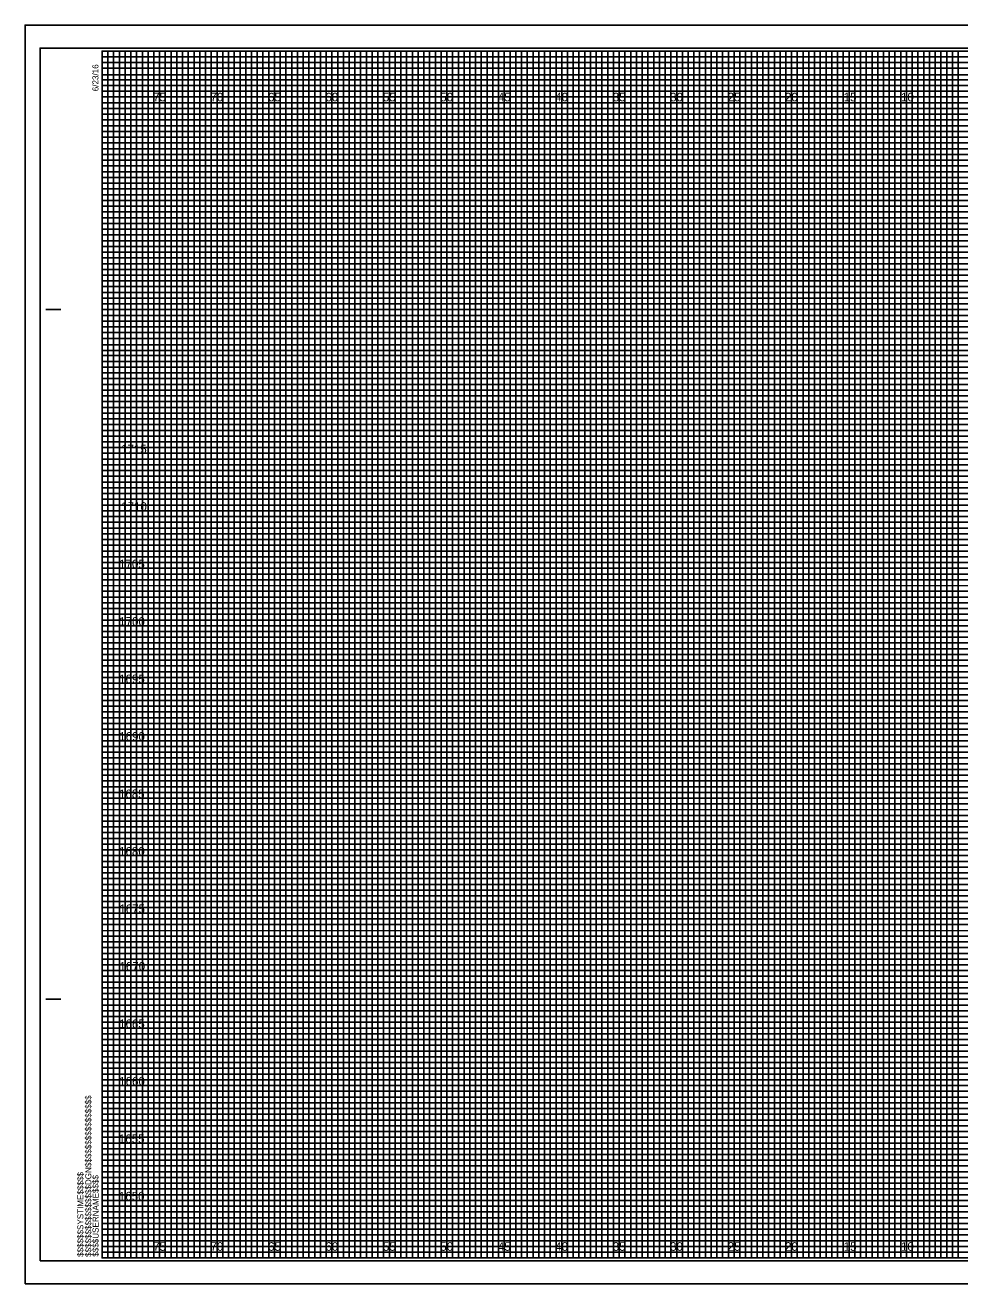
# Model space of a CAD drawing. Extents: x -407 to -239, y -3 to 766.
# Drawn here: x -407 to -325.7, y 326.6 to 436.1 of the extents above; entities that cross this region are included whole.
import ezdxf

# ---------------------------------------------------------------- set-up
doc = ezdxf.new("R2010")
doc.units = 0
for name, color, linetype in [('Raster_Level_0', 7, 'Continuous'), ('Scratch_Level_3', 7, 'Continuous'), ('Sheet Cross Section CELL', 7, 'Continuous'), ('Sheet Cross Section Grid Major CELL', 7, 'Continuous'), ('Sheet Cross Section Grid Middle CELL', 7, 'Continuous'), ('Sheet Cross Section Grid Minor 1 CELL', 7, 'Continuous'), ('Sheet Cross Section Grid Minor 2 CELL', 7, 'Continuous'), ('Sheet Cutting Line CELL', 7, 'Continuous'), ('Sheet DOT Grid CELL', 7, 'Continuous'), ('Sheet Plot Border Inside CELL', 7, 'Continuous'), ('Sheet Plot Border Outside CELL', 7, 'Continuous')]:
    doc.layers.add(name, color=color, linetype=linetype)

msp = doc.modelspace()

# ---------------------------------------------------------------- linework, layer by layer
at = {"layer": 'Sheet Cross Section CELL'}
for p, q in [((-405.22, 411.38), (-403.97, 411.38)), ((-405.17, 411.38), (-403.92, 411.38)), ((-405.22, 351.38), (-403.97, 351.38)), ((-405.17, 351.38), (-403.92, 351.38)), ((-400.32, 328.88), (-400.32, 328.88)), ((-400.32, 328.88), (-400.32, 328.88)), ((-400.32, 328.88), (-400.32, 328.88)), ((-400.32, 328.88), (-400.32, 328.88)), ((-400.32, 328.88), (-400.32, 328.88)), ((-400.32, 328.88), (-400.32, 328.88)), ((-400.32, 328.88), (-400.32, 328.88))]:
    msp.add_line(p, q, dxfattribs=at)
msp.add_lwpolyline([(-240.32, 433.88), (-400.32, 433.88), (-400.32, 328.88), (-240.32, 328.88)], close=True, dxfattribs=at)
at = {"layer": 'Sheet Cross Section Grid Major CELL'}
for p, q in [((-395.32, 433.88), (-400.32, 433.88)), ((-395.32, 328.88), (-395.32, 433.88)), ((-385.32, 433.88), (-390.32, 433.88)), ((-390.32, 433.88), (-390.32, 328.88)), ((-385.32, 328.88), (-385.32, 433.88)), ((-375.32, 433.88), (-380.32, 433.88)), ((-380.32, 433.88), (-380.32, 328.88)), ((-375.32, 328.88), (-375.32, 433.88)), ((-365.32, 433.88), (-370.32, 433.88)), ((-370.32, 433.88), (-370.32, 328.88)), ((-365.32, 328.88), (-365.32, 433.88)), ((-355.32, 433.88), (-360.32, 433.88)), ((-360.32, 433.88), (-360.32, 328.88)), ((-355.32, 328.88), (-355.32, 433.88)), ((-345.32, 433.88), (-350.32, 433.88)), ((-350.32, 433.88), (-350.32, 328.88)), ((-345.32, 328.88), (-345.32, 433.88)), ((-335.32, 433.88), (-340.32, 433.88)), ((-340.32, 433.88), (-340.32, 328.88)), ((-335.32, 328.88), (-335.32, 433.88)), ((-325.32, 433.88), (-330.32, 433.88)), ((-330.32, 433.88), (-330.32, 328.88)), ((-390.32, 328.88), (-395.32, 328.88)), ((-380.32, 328.88), (-385.32, 328.88)), ((-370.32, 328.88), (-375.32, 328.88)), ((-360.32, 328.88), (-365.32, 328.88)), ((-350.32, 328.88), (-355.32, 328.88)), ((-340.32, 328.88), (-345.32, 328.88)), ((-330.32, 328.88), (-335.32, 328.88))]:
    msp.add_line(p, q, dxfattribs=at)
for points in [[(-400.32, 428.88), (-240.32, 428.88), (-240.32, 423.88), (-400.32, 423.88)], [(-400.32, 418.88), (-240.32, 418.88), (-240.32, 413.88), (-400.32, 413.88)], [(-400.32, 408.88), (-240.32, 408.88), (-240.32, 403.88), (-400.32, 403.88)], [(-400.32, 398.88), (-240.32, 398.88), (-240.32, 393.88), (-400.32, 393.88)], [(-400.32, 388.88), (-240.32, 388.88), (-240.32, 383.88), (-400.32, 383.88)], [(-400.32, 378.88), (-240.32, 378.88), (-240.32, 373.88), (-400.32, 373.88)], [(-400.32, 368.88), (-240.32, 368.88), (-240.32, 363.88), (-400.32, 363.88)], [(-400.32, 358.88), (-240.32, 358.88), (-240.32, 353.88), (-400.32, 353.88)], [(-400.32, 348.88), (-240.32, 348.88), (-240.32, 343.88), (-400.32, 343.88)], [(-400.32, 338.88), (-240.32, 338.88), (-240.32, 333.88), (-400.32, 333.88)]]:
    msp.add_lwpolyline(points, dxfattribs=at)
at = {"layer": 'Sheet Cross Section Grid Middle CELL'}
for points in [[(-400.32, 433.88), (-397.82, 433.88), (-397.82, 328.88), (-392.82, 328.88), (-392.82, 433.88), (-387.82, 433.88), (-387.82, 328.88), (-382.82, 328.88), (-382.82, 433.88), (-377.82, 433.88), (-377.82, 328.88), (-372.82, 328.88), (-372.82, 433.88), (-367.82, 433.88), (-367.82, 328.88), (-362.82, 328.88), (-362.82, 433.88), (-357.82, 433.88), (-357.82, 328.88), (-352.82, 328.88), (-352.82, 433.88), (-347.82, 433.88), (-347.82, 328.88), (-342.82, 328.88), (-342.82, 433.88), (-337.82, 433.88), (-337.82, 328.88), (-332.82, 328.88), (-332.82, 433.88), (-327.82, 433.88), (-327.82, 328.88), (-322.82, 328.88)], [(-400.32, 431.38), (-262.82, 431.38)], [(-400.32, 421.38), (-240.32, 421.38), (-240.32, 426.38), (-400.32, 426.38)], [(-400.32, 411.38), (-240.32, 411.38), (-240.32, 416.38), (-400.32, 416.38)], [(-400.32, 401.38), (-240.32, 401.38), (-240.32, 406.38), (-400.32, 406.38)], [(-400.32, 391.38), (-240.32, 391.38), (-240.32, 396.38), (-400.32, 396.38)], [(-400.32, 381.38), (-240.32, 381.38), (-240.32, 386.38), (-400.32, 386.38)], [(-400.32, 371.38), (-240.32, 371.38), (-240.32, 376.38), (-400.32, 376.38)], [(-400.32, 361.38), (-240.32, 361.38), (-240.32, 366.38), (-400.32, 366.38)], [(-400.32, 351.38), (-240.32, 351.38), (-240.32, 356.38), (-400.32, 356.38)], [(-400.32, 341.38), (-240.32, 341.38), (-240.32, 346.38), (-400.32, 346.38)], [(-400.32, 331.38), (-240.32, 331.38), (-240.32, 336.38), (-400.32, 336.38)]]:
    msp.add_lwpolyline(points, dxfattribs=at)
at = {"layer": 'Sheet Cross Section Grid Minor 1 CELL'}
for p, q in [((-400.32, 433.38), (-270.32, 433.38)), ((-270.32, 432.87), (-400.32, 432.87)), ((-400.32, 432.87), (-400.32, 432.38)), ((-400.32, 432.38), (-270.32, 432.38)), ((-270.32, 431.82), (-400.32, 431.82)), ((-400.32, 431.82), (-400.32, 430.88)), ((-400.32, 430.88), (-240.32, 430.88))]:
    msp.add_line(p, q, dxfattribs=at)
for points in [[(-400.32, 430.38), (-265.32, 430.38), (-240.32, 430.38), (-240.32, 429.88), (-400.32, 429.88)], [(-400.32, 429.38), (-240.32, 429.38), (-240.32, 428.38), (-400.32, 428.38)], [(-400.32, 427.88), (-240.32, 427.88), (-240.32, 427.38), (-400.32, 427.37)], [(-400.32, 426.88), (-240.32, 426.88), (-240.32, 425.88), (-400.32, 425.88)], [(-400.32, 425.38), (-240.32, 425.38), (-240.32, 424.88), (-400.32, 424.88)], [(-400.32, 424.38), (-240.32, 424.38), (-240.32, 423.38), (-400.32, 423.38)], [(-400.32, 422.88), (-240.32, 422.88), (-240.32, 422.38), (-400.32, 422.38)], [(-400.32, 421.88), (-240.32, 421.88), (-240.32, 420.88), (-400.32, 420.88)], [(-400.32, 420.38), (-240.32, 420.38), (-240.32, 419.88), (-400.32, 419.88)], [(-400.32, 419.38), (-240.32, 419.38), (-240.32, 418.38), (-400.32, 418.38)], [(-400.32, 417.88), (-240.32, 417.88), (-240.32, 417.38), (-400.32, 417.38)], [(-400.32, 416.88), (-240.32, 416.88), (-240.32, 415.85), (-240.32, 415.38), (-240.32, 414.88), (-400.32, 414.88)], [(-400.32, 415.88), (-240.32, 415.88), (-240.32, 415.38), (-400.32, 415.38)], [(-400.32, 414.38), (-240.32, 414.38), (-240.32, 413.38), (-400.32, 413.39)], [(-400.32, 413.39), (-240.32, 413.38), (-240.32, 412.88), (-400.32, 412.88)], [(-400.32, 412.38), (-240.32, 412.38), (-240.32, 411.88), (-400.32, 411.88)], [(-400.32, 410.88), (-240.32, 410.88), (-240.32, 410.38), (-400.32, 410.38)], [(-400.32, 409.88), (-240.32, 409.88), (-240.32, 409.38), (-400.32, 409.38)], [(-400.35, 408.32), (-240.32, 408.32), (-240.32, 407.82), (-400.35, 407.82)], [(-400.32, 407.38), (-240.32, 407.38), (-240.32, 406.88), (-400.32, 406.88)], [(-400.32, 405.88), (-240.32, 405.88), (-240.32, 405.38), (-400.32, 405.38)], [(-400.32, 404.88), (-240.32, 404.88), (-240.32, 404.38), (-400.32, 404.38)], [(-400.32, 403.38), (-240.32, 403.38), (-240.32, 402.88), (-400.32, 402.88)], [(-400.32, 402.38), (-240.32, 402.38), (-240.32, 401.88), (-400.32, 401.88)], [(-400.32, 400.88), (-240.32, 400.88), (-240.32, 400.38), (-400.32, 400.38)], [(-400.32, 399.88), (-240.32, 399.88), (-240.32, 399.38), (-400.32, 399.38)], [(-400.32, 398.38), (-240.32, 398.38), (-240.32, 397.87), (-400.32, 397.88)], [(-400.32, 397.38), (-240.32, 397.38), (-240.32, 396.88), (-400.32, 396.88)], [(-400.32, 395.88), (-240.32, 395.88), (-240.32, 395.38), (-400.32, 395.38)], [(-400.32, 394.88), (-240.32, 394.88), (-240.32, 394.38), (-400.32, 394.38)], [(-400.32, 393.38), (-240.32, 393.38), (-240.32, 392.88), (-400.32, 392.88)], [(-400.32, 392.38), (-240.32, 392.38), (-240.32, 391.88), (-400.32, 391.88)], [(-400.32, 390.88), (-240.32, 390.88), (-240.32, 390.38), (-400.32, 390.38)], [(-400.32, 389.88), (-240.32, 389.88), (-240.32, 389.38), (-400.32, 389.38)], [(-400.32, 388.38), (-240.32, 388.38), (-240.32, 387.88), (-400.32, 387.88)], [(-400.32, 387.37), (-240.28, 387.33), (-240.32, 386.88), (-400.32, 386.88)], [(-400.32, 385.88), (-240.32, 385.88), (-240.32, 385.38), (-400.32, 385.38)], [(-400.32, 384.88), (-240.32, 384.88), (-240.32, 384.38), (-400.32, 384.38)], [(-400.32, 383.38), (-240.32, 383.38), (-240.32, 382.88), (-400.32, 382.88)], [(-400.32, 382.38), (-240.32, 382.38), (-240.32, 381.88), (-400.32, 381.88)], [(-400.32, 380.88), (-240.32, 380.88), (-240.32, 380.38), (-400.32, 380.38)], [(-400.32, 379.88), (-240.32, 379.88), (-240.32, 379.38), (-400.32, 379.38)], [(-400.32, 378.38), (-240.32, 378.38), (-240.32, 377.88), (-400.32, 377.88)], [(-400.32, 377.38), (-240.32, 377.38), (-240.32, 376.88), (-400.32, 376.88)], [(-400.32, 375.88), (-240.32, 375.88), (-240.32, 375.38), (-400.32, 375.38)], [(-400.32, 374.88), (-240.32, 374.88), (-240.32, 374.38), (-400.32, 374.38)], [(-400.32, 373.38), (-240.32, 373.38), (-240.32, 372.88), (-400.32, 372.88)], [(-400.32, 372.38), (-240.32, 372.38), (-240.32, 371.88), (-400.32, 371.88)], [(-400.32, 370.88), (-240.32, 370.88), (-240.32, 370.38), (-400.32, 370.38)], [(-400.32, 369.88), (-240.32, 369.88), (-240.32, 369.38), (-400.32, 369.38)], [(-400.32, 368.38), (-240.32, 368.38), (-240.32, 367.87), (-400.32, 367.88)], [(-400.32, 367.38), (-240.32, 367.38), (-240.32, 366.88), (-400.32, 366.88)], [(-400.32, 365.88), (-240.32, 365.88), (-240.32, 365.38), (-400.32, 365.38)], [(-400.32, 364.88), (-240.32, 364.88), (-240.32, 364.38), (-400.32, 364.38)], [(-400.32, 363.38), (-240.32, 363.38), (-240.32, 362.88), (-400.32, 362.88)], [(-400.32, 362.38), (-240.32, 362.38), (-240.32, 361.88), (-400.32, 361.88)], [(-400.32, 360.88), (-240.32, 360.88), (-240.32, 360.38), (-400.32, 360.38)], [(-400.32, 359.88), (-240.32, 359.88), (-240.32, 359.38), (-400.32, 359.38)], [(-400.32, 358.38), (-240.32, 358.38), (-240.32, 357.88), (-400.32, 357.88)], [(-400.32, 357.37), (-240.28, 357.33), (-240.32, 356.88), (-400.32, 356.88)], [(-400.32, 355.88), (-240.32, 355.88), (-240.32, 355.38), (-400.32, 355.38)], [(-400.32, 354.88), (-240.32, 354.88), (-240.32, 354.38), (-400.32, 354.38)], [(-400.32, 353.38), (-240.32, 353.38), (-240.32, 352.88), (-400.32, 352.88)], [(-400.32, 352.38), (-240.32, 352.38), (-240.32, 351.88), (-400.32, 351.88)], [(-400.32, 350.88), (-240.32, 350.88), (-240.32, 350.38), (-400.32, 350.38)], [(-400.32, 349.88), (-240.32, 349.88), (-240.32, 349.38), (-400.32, 349.38)], [(-400.32, 348.38), (-240.32, 348.38), (-240.32, 347.88), (-400.32, 347.88)], [(-400.32, 347.38), (-240.32, 347.38), (-240.32, 346.88), (-400.32, 346.88)], [(-400.32, 345.88), (-240.32, 345.88), (-240.32, 345.38), (-400.32, 345.38)], [(-400.32, 344.88), (-240.32, 344.88), (-240.32, 344.38), (-400.32, 344.38)], [(-400.32, 343.38), (-240.32, 343.38), (-240.32, 342.88), (-400.32, 342.88)], [(-400.32, 342.38), (-240.32, 342.38), (-240.32, 341.88), (-400.32, 341.88)], [(-400.32, 340.88), (-240.32, 340.88), (-240.32, 340.38), (-400.32, 340.38)], [(-400.32, 339.88), (-240.32, 339.88), (-240.32, 339.38), (-400.32, 339.38)], [(-400.32, 338.38), (-240.32, 338.38), (-240.32, 337.88), (-400.32, 337.88)], [(-400.32, 337.38), (-240.32, 337.38), (-240.32, 336.88), (-400.32, 336.88)], [(-400.32, 335.88), (-240.32, 335.88), (-240.32, 335.38), (-400.32, 335.38)], [(-400.32, 334.88), (-240.32, 334.88), (-240.32, 334.38), (-400.32, 334.38)], [(-400.32, 333.38), (-240.32, 333.38), (-240.32, 332.88), (-400.32, 332.88)], [(-400.32, 332.38), (-240.32, 332.38), (-240.32, 331.88), (-400.32, 331.88)], [(-400.32, 330.88), (-240.32, 330.88), (-240.32, 330.38), (-400.32, 330.38)], [(-400.32, 329.88), (-240.32, 329.88), (-240.32, 329.38), (-400.32, 329.38)]]:
    msp.add_lwpolyline(points, dxfattribs=at)
at = {"layer": 'Sheet Cross Section Grid Minor 2 CELL'}
for points in [[(-400.32, 328.88), (-399.82, 328.88), (-399.82, 433.88), (-399.32, 433.88), (-399.32, 328.88)], [(-399.32, 328.88), (-398.82, 328.88), (-398.82, 433.88), (-398.32, 433.88), (-398.32, 328.88)], [(-397.82, 328.88), (-397.32, 328.88), (-397.32, 433.88), (-396.82, 433.88), (-396.82, 328.88)], [(-396.82, 328.88), (-396.32, 328.88), (-396.32, 433.88), (-395.82, 433.88), (-395.82, 328.88)], [(-395.32, 328.88), (-394.82, 328.88), (-394.82, 433.88), (-394.32, 433.88), (-394.32, 328.88)], [(-394.32, 328.88), (-393.82, 328.88), (-393.82, 433.88), (-393.32, 433.88), (-393.32, 328.88)], [(-392.82, 328.88), (-392.32, 328.88), (-392.32, 433.88), (-391.82, 433.88), (-391.82, 328.88)], [(-391.82, 328.88), (-391.32, 328.88), (-391.32, 433.88), (-390.82, 433.88), (-390.82, 328.88)], [(-390.32, 328.88), (-389.82, 328.88), (-389.82, 433.88), (-389.32, 433.88), (-389.32, 328.88)], [(-389.32, 328.88), (-388.82, 328.88), (-388.82, 433.88), (-388.32, 433.88), (-388.32, 328.88)], [(-387.82, 328.88), (-387.32, 328.88), (-387.32, 433.88), (-386.82, 433.88), (-386.82, 328.88)], [(-386.82, 328.88), (-386.32, 328.88), (-386.32, 433.88), (-385.82, 433.88), (-385.82, 328.88)], [(-385.32, 328.88), (-384.82, 328.88), (-384.82, 433.88), (-384.32, 433.88), (-384.32, 328.88)], [(-384.32, 328.88), (-383.82, 328.88), (-383.82, 433.88), (-383.32, 433.88), (-383.32, 328.88)], [(-382.82, 328.88), (-382.32, 328.88), (-382.32, 433.88), (-381.82, 433.88), (-381.82, 328.88)], [(-381.82, 328.88), (-381.32, 328.88), (-381.32, 433.88), (-380.82, 433.88), (-380.82, 328.88)], [(-380.32, 328.88), (-379.82, 328.88), (-379.82, 433.88), (-379.32, 433.88), (-379.32, 328.88)], [(-379.32, 328.88), (-378.82, 328.88), (-378.82, 433.88), (-378.32, 433.88), (-378.32, 328.88)], [(-377.82, 328.88), (-377.32, 328.88), (-377.32, 433.88), (-376.82, 433.88), (-376.82, 328.88)], [(-376.82, 328.88), (-376.32, 328.88), (-376.32, 433.88), (-375.82, 433.88), (-375.82, 328.88)], [(-375.32, 328.88), (-374.82, 328.88), (-374.82, 433.88), (-374.32, 433.88), (-374.32, 328.88)], [(-374.32, 328.88), (-373.82, 328.88), (-373.82, 433.88), (-373.32, 433.88), (-373.32, 328.88)], [(-372.82, 328.88), (-372.32, 328.88), (-372.32, 433.88), (-371.82, 433.88), (-371.82, 328.88)], [(-371.82, 328.88), (-371.32, 328.88), (-371.32, 433.88), (-370.82, 433.88), (-370.82, 328.88)], [(-370.32, 328.88), (-369.82, 328.88), (-369.82, 433.88), (-369.32, 433.88), (-369.32, 328.88)], [(-369.32, 328.88), (-368.82, 328.88), (-368.82, 433.88), (-368.32, 433.88), (-368.32, 328.88)], [(-367.82, 328.88), (-367.32, 328.88), (-367.32, 433.88), (-366.82, 433.88), (-366.82, 328.88)], [(-366.82, 328.88), (-366.32, 328.88), (-366.32, 433.88), (-365.82, 433.88), (-365.82, 328.88)], [(-365.32, 328.88), (-364.82, 328.88), (-364.82, 433.88), (-364.32, 433.88), (-364.32, 328.88)], [(-364.32, 328.88), (-363.82, 328.88), (-363.82, 433.88), (-363.32, 433.88), (-363.32, 328.88)], [(-362.82, 328.88), (-362.32, 328.88), (-362.32, 433.88), (-361.82, 433.88), (-361.82, 328.88)], [(-361.82, 328.88), (-361.32, 328.88), (-361.32, 433.88), (-360.82, 433.88), (-360.82, 328.88)], [(-360.32, 328.88), (-359.82, 328.88), (-359.82, 433.88), (-359.32, 433.88), (-359.32, 328.88)], [(-359.32, 328.88), (-358.82, 328.88), (-358.82, 433.88), (-358.32, 433.88), (-358.32, 328.88)], [(-357.82, 328.88), (-357.32, 328.88), (-357.32, 433.88), (-356.82, 433.88), (-356.82, 328.88)], [(-356.82, 328.88), (-356.32, 328.88), (-356.32, 433.88), (-355.82, 433.88), (-355.82, 328.88)], [(-355.32, 328.88), (-354.82, 328.88), (-354.82, 433.88), (-354.32, 433.88), (-354.32, 328.88)], [(-354.32, 328.88), (-353.82, 328.88), (-353.82, 433.88), (-353.32, 433.88), (-353.32, 328.88)], [(-352.82, 328.88), (-352.32, 328.88), (-352.32, 433.88), (-351.82, 433.88), (-351.82, 328.88)], [(-351.82, 328.88), (-351.32, 328.88), (-351.32, 433.88), (-350.82, 433.88), (-350.82, 328.88)], [(-350.32, 328.88), (-349.82, 328.88), (-349.82, 433.88), (-349.32, 433.88), (-349.32, 328.88)], [(-349.32, 328.88), (-348.82, 328.88), (-348.82, 433.88), (-348.32, 433.88), (-348.32, 328.88)], [(-347.82, 328.88), (-347.32, 328.88), (-347.32, 433.88), (-346.82, 433.88), (-346.82, 328.88)], [(-346.82, 328.88), (-346.32, 328.88), (-346.32, 433.88), (-345.82, 433.88), (-345.82, 328.88)], [(-345.32, 328.88), (-344.82, 328.88), (-344.82, 433.88), (-344.32, 433.88), (-344.32, 328.88)], [(-344.32, 328.88), (-343.82, 328.88), (-343.82, 433.88), (-343.32, 433.88), (-343.32, 328.88)], [(-342.82, 328.88), (-342.32, 328.88), (-342.32, 433.88), (-341.82, 433.88), (-341.82, 328.88)], [(-341.82, 328.88), (-341.32, 328.88), (-341.32, 433.88), (-340.82, 433.88), (-340.82, 328.88)], [(-340.32, 328.88), (-339.82, 328.88), (-339.82, 433.88), (-339.32, 433.88), (-339.32, 328.88)], [(-339.32, 328.88), (-338.82, 328.88), (-338.82, 433.88), (-338.32, 433.88), (-338.32, 328.88)], [(-337.82, 328.88), (-337.32, 328.88), (-337.32, 433.88), (-336.82, 433.88), (-336.82, 328.88)], [(-336.82, 328.88), (-336.32, 328.88), (-336.32, 433.88), (-335.82, 433.88), (-335.82, 328.88)], [(-335.32, 328.88), (-334.82, 328.88), (-334.82, 433.88), (-334.32, 433.88), (-334.32, 328.88)], [(-334.32, 328.88), (-333.82, 328.88), (-333.82, 433.88), (-333.32, 433.88), (-333.32, 328.88)], [(-332.82, 328.88), (-332.32, 328.88), (-332.32, 433.88), (-331.82, 433.88), (-331.82, 328.88)], [(-331.82, 328.88), (-331.32, 328.88), (-331.32, 433.88), (-330.82, 433.88), (-330.82, 328.88)], [(-330.32, 328.88), (-329.82, 328.88), (-329.82, 433.88), (-329.32, 433.88), (-329.32, 328.88)], [(-329.32, 328.88), (-328.82, 328.88), (-328.82, 433.88), (-328.32, 433.88), (-328.32, 328.88)], [(-327.82, 328.88), (-327.32, 328.88), (-327.32, 433.88), (-326.82, 433.88), (-326.82, 328.88)], [(-326.82, 328.88), (-326.32, 328.88), (-326.32, 433.88), (-325.82, 433.88), (-325.82, 328.88)]]:
    msp.add_lwpolyline(points, dxfattribs=at)
at = {"layer": 'Sheet Cutting Line CELL'}
for p, q in [((-238.67, 436.13), (-407.02, 436.13)), ((-407.02, 436.13), (-407.02, 326.63)), ((-407.02, 326.63), (-238.67, 326.63))]:
    msp.add_line(p, q, dxfattribs=at)
at = {"layer": 'Sheet DOT Grid CELL'}
for p, q in [((-395.32, 328.88), (-395.32, 433.88)), ((-390.32, 328.88), (-390.32, 433.88)), ((-385.32, 328.88), (-385.32, 433.88)), ((-380.32, 328.88), (-380.32, 433.88)), ((-375.32, 328.88), (-375.32, 433.88)), ((-370.32, 328.88), (-370.32, 433.88)), ((-365.32, 328.88), (-365.32, 433.88)), ((-360.32, 328.88), (-360.32, 433.88)), ((-355.32, 328.88), (-355.32, 433.88)), ((-350.32, 328.88), (-350.32, 433.88)), ((-345.32, 328.88), (-345.32, 433.88)), ((-340.32, 328.88), (-340.32, 433.88)), ((-335.32, 328.88), (-335.32, 433.88)), ((-330.32, 328.88), (-330.32, 433.88)), ((-400.32, 428.88), (-240.32, 428.88)), ((-400.32, 423.88), (-240.32, 423.88)), ((-400.32, 418.88), (-240.32, 418.88)), ((-400.32, 413.88), (-240.32, 413.88)), ((-400.32, 408.88), (-240.32, 408.88)), ((-400.32, 403.88), (-240.32, 403.88)), ((-400.32, 398.88), (-240.32, 398.88)), ((-400.32, 393.88), (-240.32, 393.88)), ((-400.32, 388.88), (-240.32, 388.88)), ((-400.32, 383.88), (-240.32, 383.88)), ((-400.32, 378.88), (-240.32, 378.88)), ((-400.32, 373.88), (-240.32, 373.88)), ((-400.32, 368.88), (-240.32, 368.88)), ((-400.32, 363.88), (-240.32, 363.88)), ((-400.32, 358.88), (-240.32, 358.88)), ((-400.32, 353.88), (-240.32, 353.88)), ((-400.32, 348.88), (-240.32, 348.88)), ((-400.32, 343.88), (-240.32, 343.88)), ((-400.32, 338.88), (-240.32, 338.88)), ((-400.32, 333.88), (-240.32, 333.88))]:
    msp.add_line(p, q, dxfattribs=at)
at = {"layer": 'Sheet Plot Border Inside CELL'}
msp.add_lwpolyline([(-405.72, 328.63), (-239.12, 328.63), (-239.12, 434.13), (-405.72, 434.13)], close=True, dxfattribs=at)
at = {"layer": 'Sheet Plot Border Outside CELL'}
msp.add_lwpolyline([(-407.02, 326.63), (-238.67, 326.63), (-238.67, 436.13), (-407.02, 436.13)], close=True, dxfattribs=at)

# ---------------------------------------------------------------- texts
at = {"layer": 'Raster_Level_0'}
for s, p in [('75', (-395.88, 429.5)), ('70', (-390.89, 429.5)), ('65', (-385.88, 429.5)), ('60', (-380.89, 429.5)), ('55', (-375.88, 429.5)), ('50', (-370.89, 429.5)), ('45', (-365.88, 429.5)), ('40', (-360.89, 429.5)), ('35', (-355.88, 429.5)), ('30', (-350.89, 429.5)), ('25', (-345.88, 429.5)), ('20', (-340.89, 429.5)), ('15', (-335.79, 429.5)), ('10', (-330.8, 429.5)), ('75', (-395.88, 329.5)), ('70', (-390.89, 329.5)), ('65', (-385.88, 329.5)), ('60', (-380.89, 329.5)), ('55', (-375.88, 329.5)), ('50', (-370.89, 329.5)), ('45', (-365.88, 329.5)), ('40', (-360.89, 329.5)), ('35', (-355.88, 329.5)), ('30', (-350.89, 329.5)), ('25', (-345.88, 329.5)), ('20', (-340.89, 329.5)), ('15', (-335.79, 329.5)), ('10', (-330.8, 329.5))]:
    msp.add_text(s, height=0.75, dxfattribs=at).set_placement(p)
at = {"layer": 'Scratch_Level_3'}
for s, p in [('1715', (-398.67, 398.88)), ('1710', (-398.66, 393.88)), ('1705', (-398.84, 388.88)), ('1700', (-398.83, 383.88)), ('1695', (-398.84, 378.88)), ('1690', (-398.83, 373.88)), ('1685', (-398.85, 368.88)), ('1680', (-398.84, 363.88)), ('1675', (-398.82, 358.88)), ('1670', (-398.81, 353.88)), ('1665', (-398.84, 348.88)), ('1660', (-398.83, 343.88)), ('1655', (-398.86, 338.88)), ('1650', (-398.86, 333.88))]:
    msp.add_text(s, height=0.75, dxfattribs=at).set_placement(p)
at = {"layer": 'Sheet Cross Section CELL'}
for s, p in [('6/23/16', (-400.64, 430.38)), ('$$$$$$$$$$$$$$$$DGN$$$$$$$$$$$$$$$$', (-401.26, 328.97)), ('$$$$$$SYSTIME$$$$$', (-401.95, 328.97)), ('$$$$USERNAME$$$$', (-400.63, 328.99))]:
    msp.add_text(s, height=0.525, rotation=90, dxfattribs=at).set_placement(p)

doc.saveas('drawing.dxf')
